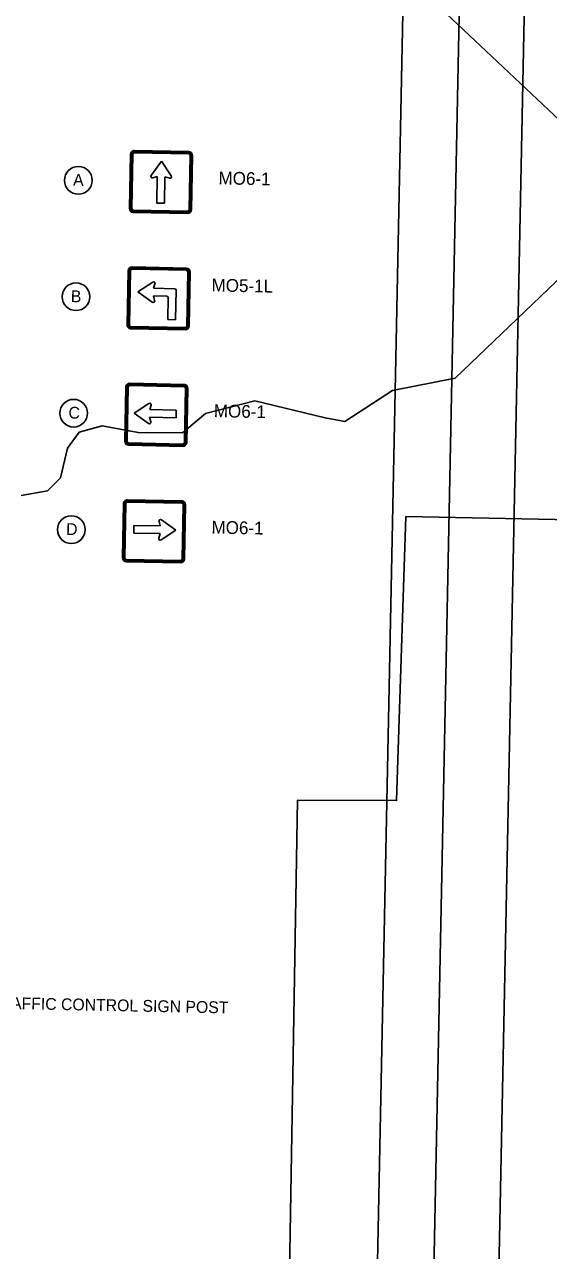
# Model space of a CAD drawing. Extents: x 331323 to 388339, y 121519 to 205315.
# Drawn here: x 369003 to 371668, y 128453 to 134686 of the extents above; entities that cross this region are included whole.
import ezdxf

# ---------------------------------------------------------------- set-up
doc = ezdxf.new("R2010")
doc.units = 0
for name, color, linetype in [('CA-TEXT', 7, 'Continuous'), ('Level 21', 7, 'Continuous'), ('Level 57', 7, 'Continuous'), ('P_RDWY_Text', 7, 'Continuous'), ('P_SGN_Cell', 7, 'Continuous'), ('PLT_Sheet_Border', 7, 'Continuous'), ('PLT_Sheet_Info', 7, 'Continuous')]:
    doc.layers.add(name, color=color, linetype=linetype)

msp = doc.modelspace()

# ---------------------------------------------------------------- linework, layer by layer
at = {"layer": 'CA-TEXT'}
for centre in [(369276.6, 133894), (369264.7, 133302.1), (369252.8, 132710.1), (369240.8, 132118.2)]:
    msp.add_circle(centre, 70.4, dxfattribs=at)
at = {"layer": 'Level 21'}
msp.add_lwpolyline([(375076, 132102.1), (370942.7, 132184.5), (370894.9, 130740.5), (370391.8, 130742.4), (370319, 126443.1), (367794.6, 126431), (367808.5, 132230.6), (366119.6, 132232.6), (366135.9, 131512.6), (366392.2, 131511.6), (366389.5, 130783.4), (366030.6, 131090.7), (365085.3, 131111.7), (365089.7, 131495.3), (364322.8, 131506.6), (364297.4, 130439.9), (364588.5, 130440.1), (364573.4, 129673), (363928.9, 129678.5), (363911.7, 128375.4), (362625.6, 128409.6), (362593.8, 121807)], dxfattribs=at)
at = {"layer": 'Level 57'}
for points in [[(366907.1, 140244.2), (366940.2, 140210.6), (366955.4, 140052.1), (366988.1, 139985.1), (367035.4, 139684.7), (367213.5, 139108.1), (367236.6, 138899.5), (367318.2, 138698.8), (367417, 138556.2), (367681.2, 138270.5), (367771.2, 138086.3), (367834.3, 137694.1), (367933.8, 137626.5), (368233.7, 137590.5), (368324.8, 137523), (368390.2, 137380.7), (368778.5, 136985.5), (369580.4, 136219.9), (370688.4, 135176.5), (371812.8, 134116.3), (371829.2, 134082.8)], [(368985.4, 132291.8), (369119.1, 132315.6), (369186.4, 132381.7), (369221.1, 132531.4), (369280.3, 132614.2), (369397.3, 132646.5), (369580.5, 132611.5), (369805.7, 132609.4), (369923.3, 132708.4), (370174.1, 132772.8), (370531.9, 132686.2), (370631.9, 132668.6), (370875.2, 132824.8), (371192.7, 132888.6), (371823.7, 133491.2)]]:
    msp.add_lwpolyline(points, dxfattribs=at)
at = {"layer": 'P_RDWY_Text'}
msp.add_lwpolyline([(354597.6, 137585.1), (371594.2, 137242.8), (371372.7, 126245), (354376.1, 126587.3)], close=True, dxfattribs=at)
at = {"layer": 'P_SGN_Cell'}
for p, q in [((369542.2, 134026.5), (369536.7, 133751)), ((369547.5, 134026.4), (369541.9, 133750.8)), ((369554, 134026.3), (369548.5, 133750.7)), ((369562, 134034), (369837.6, 134028.5)), ((369562.2, 134040.6), (369837.7, 134035)), ((369837.8, 134040.3), (369562.3, 134045.8)), ((369699, 133991.9), (369646.4, 133918.6)), ((369748.6, 133916.6), (369699, 133991.9)), ((369845.3, 134020.4), (369839.8, 133744.9)), ((369851.9, 134020.3), (369846.3, 133744.7)), ((369851.6, 133744.6), (369857.1, 134020.2)), ((369655, 133906.4), (369677.7, 133912.8)), ((369677.7, 133912.8), (369675, 133778.4)), ((369714.4, 133777.6), (369717.1, 133912)), ((369717.1, 133912), (369739.6, 133904.7)), ((369675, 133778.4), (369714.4, 133777.6)), ((369555.9, 133730.9), (369831.5, 133725.3)), ((369556, 133736.1), (369831.6, 133730.6)), ((369556.2, 133742.7), (369831.7, 133737.1)), ((369530.3, 133434.6), (369524.7, 133159)), ((369530, 133158.9), (369535.5, 133434.5)), ((369536.5, 133158.8), (369542.1, 133434.3)), ((369550.1, 133442.1), (369825.7, 133436.5)), ((369550.3, 133448.6), (369825.8, 133443.1)), ((369825.9, 133448.3), (369550.4, 133453.9)), ((369827.9, 133152.9), (369833.4, 133428.5)), ((369834.4, 133152.8), (369840, 133428.3)), ((369839.7, 133152.7), (369845.2, 133428.2)), ((369579.3, 133327.3), (369654.6, 133376.9)), ((369666.4, 133367.9), (369659.1, 133345.3)), ((369659.1, 133345.3), (369766, 133343.2)), ((369652.6, 133274.7), (369579.3, 133327.3)), ((369727.2, 133304.6), (369658.4, 133306)), ((369658.4, 133306), (369664.7, 133283.2)), ((369731.4, 133186.3), (369733.6, 133297.9)), ((369773.8, 133335.1), (369770.8, 133185.6)), ((369770.8, 133185.6), (369731.4, 133186.3)), ((369544, 133138.9), (369819.6, 133133.4)), ((369544.1, 133144.2), (369819.7, 133138.6)), ((369544.3, 133150.7), (369819.8, 133145.2)), ((369518.4, 132842.6), (369512.8, 132567.1)), ((369523.6, 132842.5), (369518.1, 132567)), ((369530.2, 132842.4), (369524.6, 132566.8)), ((369538.2, 132850.1), (369813.8, 132844.6)), ((369538.3, 132856.7), (369813.9, 132851.1)), ((369814, 132856.4), (369538.4, 132861.9)), ((369821.5, 132836.5), (369815.9, 132561)), ((369828, 132836.4), (369822.5, 132560.8)), ((369827.7, 132560.7), (369833.3, 132836.3)), ((369635.2, 132760), (369559.9, 132710.4)), ((369639.8, 132728.5), (369647.1, 132751)), ((369774.2, 132725.7), (369639.8, 132728.5)), ((369773.4, 132686.4), (369774.2, 132725.7)), ((369559.9, 132710.4), (369633.2, 132657.8)), ((369645.4, 132666.3), (369639, 132689.1)), ((369639, 132689.1), (369773.4, 132686.4)), ((369532.1, 132547), (369807.7, 132541.4)), ((369532.2, 132552.2), (369807.8, 132546.7)), ((369532.3, 132558.8), (369807.9, 132553.2)), ((369506.4, 132250.7), (369500.9, 131975.1)), ((369511.7, 132250.6), (369506.1, 131975)), ((369518.2, 132250.4), (369512.7, 131974.9)), ((369526.3, 132258.2), (369801.8, 132252.6)), ((369526.4, 132264.7), (369802, 132259.2)), ((369802.1, 132264.4), (369526.5, 132270)), ((369809.6, 132244.6), (369804, 131969)), ((369816.1, 132244.4), (369810.6, 131968.9)), ((369815.8, 131968.8), (369821.4, 132244.3)), ((369687, 132159.9), (369693.4, 132137.1)), ((369772.4, 132115.8), (369699.1, 132168.4)), ((369558.9, 132139.8), (369558.1, 132100.5)), ((369558.1, 132100.5), (369692.6, 132097.8)), ((369693.4, 132137.1), (369558.9, 132139.8)), ((369692.6, 132097.8), (369685.3, 132075.2)), ((369697.1, 132066.2), (369772.4, 132115.8)), ((369520.2, 131955), (369795.7, 131949.5)), ((369520.3, 131960.3), (369795.8, 131954.7)), ((369520.4, 131966.8), (369796, 131961.3))]:
    msp.add_line(p, q, dxfattribs=at)
for centre, radius, start, end in [((369561.9, 134026.1), 19.7, 88.84682, 178.84682), ((369561.9, 134026.1), 14.4, 88.84682, 178.84682), ((369561.9, 134026.1), 7.87, 88.84682, 178.84682), ((369837.5, 134020.6), 7.87, 358.84682, 88.84682), ((369837.5, 134020.6), 14.4, 358.84682, 88.84682), ((369837.5, 134020.6), 19.7, 59.45028, 88.84682), ((369837.5, 134020.6), 19.7, 358.84682, 88.84682), ((369652.8, 133914), 7.87, 144.31715, 285.64942), ((369742.1, 133912.2), 7.87, 252.04423, 33.3765), ((369556.3, 133750.6), 19.7, 178.84682, 268.84682), ((369556.3, 133750.6), 14.4, 178.84682, 268.84682), ((369556.3, 133750.6), 7.87, 178.84682, 268.84682), ((369831.9, 133745), 19.7, 268.84682, 358.84682), ((369831.9, 133745), 14.4, 268.84682, 358.84682), ((369831.9, 133745), 7.87, 268.84682, 358.84682), ((369550, 133434.2), 19.7, 88.84622, 178.84622), ((369550, 133434.2), 14.4, 88.84622, 178.84622), ((369550, 133434.2), 7.87, 88.84622, 178.84622), ((369825.5, 133428.6), 7.87, 358.84622, 88.84622), ((369825.5, 133428.6), 14.4, 358.84622, 88.84622), ((369825.5, 133428.6), 19.7, 358.84622, 88.84622), ((369658.9, 133370.3), 7.87, 342.04363, 123.3759), ((369765.9, 133335.3), 7.87, 358.84622, 88.84622), ((369657.2, 133281.1), 7.87, 234.31655, 15.64882), ((369727.1, 133298), 6.56, 358.84622, 88.84622), ((369544.4, 133158.6), 19.7, 178.84622, 268.84622), ((369544.4, 133158.6), 14.4, 178.84622, 268.84622), ((369544.4, 133158.6), 7.87, 178.84622, 268.84622), ((369820, 133153.1), 14.4, 268.84622, 358.84622), ((369820, 133153.1), 7.87, 268.84622, 358.84622), ((369820, 133153.1), 19.7, 268.84622, 358.84622), ((369538, 132842.2), 19.7, 88.84682, 178.84682), ((369538, 132842.2), 14.4, 88.84682, 178.84682), ((369538, 132842.2), 7.87, 88.84682, 178.84682), ((369813.6, 132836.7), 7.87, 358.84682, 88.84682), ((369813.6, 132836.7), 14.4, 358.84682, 88.84682), ((369813.6, 132836.7), 19.7, 59.45028, 88.84682), ((369813.6, 132836.7), 19.7, 358.84682, 88.84682), ((369639.6, 132753.4), 7.87, 342.04423, 123.3765), ((369637.8, 132664.2), 7.87, 234.31715, 15.64942), ((369532.5, 132566.7), 19.7, 178.84682, 268.84682), ((369532.5, 132566.7), 14.4, 178.84682, 268.84682), ((369532.5, 132566.7), 7.87, 178.84682, 268.84682), ((369808.1, 132561.1), 19.7, 268.84682, 358.84682), ((369808.1, 132561.1), 14.4, 268.84682, 358.84682), ((369808.1, 132561.1), 7.87, 268.84682, 358.84682), ((369526.1, 132250.3), 19.7, 88.84682, 178.84682), ((369526.1, 132250.3), 14.4, 88.84682, 178.84682), ((369526.1, 132250.3), 7.87, 88.84682, 178.84682), ((369801.7, 132244.7), 7.87, 358.84682, 88.84682), ((369801.7, 132244.7), 14.4, 358.84682, 88.84682), ((369801.7, 132244.7), 19.7, 59.45028, 88.84682), ((369801.7, 132244.7), 19.7, 358.84682, 88.84682), ((369694.6, 132162), 7.87, 54.31715, 195.64942), ((369692.8, 132072.8), 7.87, 162.04423, 303.3765), ((369520.6, 131974.7), 19.7, 178.84682, 268.84682), ((369520.6, 131974.7), 14.4, 178.84682, 268.84682), ((369520.6, 131974.7), 7.87, 178.84682, 268.84682), ((369796.1, 131969.2), 19.7, 268.84682, 358.84682), ((369796.1, 131969.2), 14.4, 268.84682, 358.84682), ((369796.1, 131969.2), 7.87, 268.84682, 358.84682)]:
    msp.add_arc(centre, radius, start, end, dxfattribs=at)
at = {"layer": 'PLT_Sheet_Border'}
for points in [[(354376.1, 126587.3), (371372.7, 126245), (371594.2, 137242.8), (354597.6, 137585.1)], [(354501.1, 126834.8), (371047.8, 126501.6), (371259.2, 136999.5), (354712.6, 137332.7)]]:
    msp.add_lwpolyline(points, close=True, dxfattribs=at)
at = {"layer": 'PLT_Sheet_Info'}
msp.add_line((370765.4, 126757.3), (370966.7, 136755.3), dxfattribs=at)

# ---------------------------------------------------------------- texts
at = {"layer": 'CA-TEXT'}
for s, p in [('A', (369249.6, 133867)), ('B', (369237.7, 133275)), ('C', (369225.8, 132683.1)), ('D', (369213.8, 132091.1)), ('TEMPORARY TRAFFIC CONTROL SIGN POST', (368296.6, 129693.2))]:
    msp.add_text(s, height=60, rotation=358.84682, dxfattribs=at).set_placement(p)
at = {"layer": 'P_SGN_Cell'}
for s, rotation, p in [('MO6-1', 358.84682, (369988.9, 133874)), ('MO5-1L', 358.84622, (369953.5, 133329.4)), ('MO6-1', 358.84682, (369965.1, 132690.1)), ('MO6-1', 358.84682, (369953.2, 132098.2))]:
    msp.add_text(s, height=64.8, rotation=rotation, dxfattribs=at).set_placement(p)

doc.saveas('drawing.dxf')
